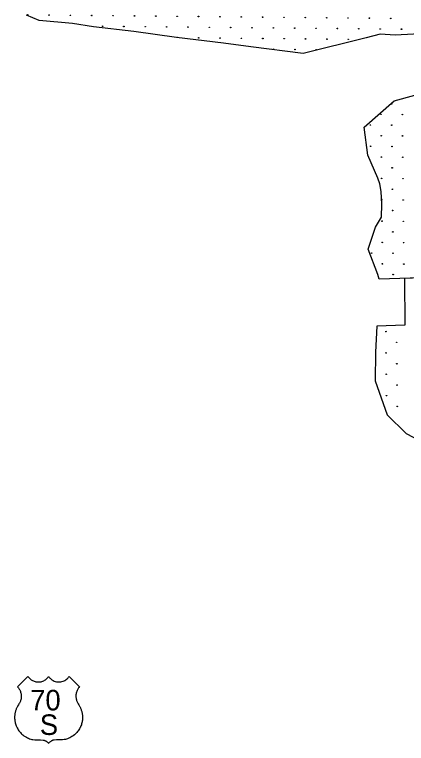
# Model space of a CAD drawing. Extents: x 1612280 to 1883141, y 560852 to 780851.
# Drawn here: x 1777552 to 1784608, y 634420 to 647547 of the extents above; entities that cross this region are included whole.
import ezdxf

# ---------------------------------------------------------------- set-up
doc = ezdxf.new("R2010")
doc.units = 0
for name, color, linetype in [('DESIGN - EROSION CONTROL - Devices', 7, 'Continuous'), ('DESIGN - SCRATCH - User 1', 7, 'Continuous'), ('SURVEY - DRAINAGE - Bridge Deck with Text', 7, 'Continuous')]:
    doc.layers.add(name, color=color, linetype=linetype)

msp = doc.modelspace()

# ---------------------------------------------------------------- linework, layer by layer
at = {"layer": 'DESIGN - EROSION CONTROL - Devices'}
for centre in [(1777788, 647542), (1777788, 647542), (1778173, 647538), (1778173, 647538), (1778557, 647534), (1778557, 647534), (1778942, 647531), (1778942, 647531), (1779326, 647527), (1779326, 647527), (1779711, 647523), (1779711, 647523), (1780095, 647520), (1780095, 647520), (1780480, 647516), (1780480, 647516), (1780864, 647512), (1780864, 647512), (1781249, 647508), (1781249, 647508), (1781634, 647505), (1781634, 647505), (1782018, 647501), (1782018, 647501), (1782403, 647497), (1782403, 647497), (1782787, 647493), (1782787, 647493), (1783172, 647490), (1783172, 647490), (1783556, 647486), (1783556, 647486), (1783941, 647482), (1783941, 647482), (1784325, 647478), (1784325, 647478), (1779136, 647337), (1779136, 647337), (1779520, 647333), (1779520, 647333), (1779905, 647329), (1779905, 647329), (1780290, 647325), (1780290, 647325), (1780674, 647322), (1780674, 647322), (1781059, 647318), (1781059, 647318), (1781443, 647314), (1781443, 647314), (1781828, 647310), (1781828, 647310), (1782212, 647307), (1782212, 647307), (1782597, 647303), (1782597, 647303), (1782981, 647299), (1782981, 647299), (1783366, 647296), (1783366, 647296), (1783750, 647292), (1783750, 647292), (1784135, 647288), (1784135, 647288), (1784520, 647284), (1784520, 647284), (1780868, 647128), (1780868, 647128), (1781253, 647124), (1781253, 647124), (1781637, 647120), (1781637, 647120), (1782022, 647116), (1782022, 647116), (1782406, 647113), (1782406, 647113), (1782791, 647109), (1782791, 647109), (1783176, 647105), (1783176, 647105), (1783560, 647101), (1783560, 647101), (1782216, 646922), (1782216, 646922), (1782601, 646918), (1782601, 646918), (1782985, 646915), (1782985, 646915), (1784340, 645940), (1784340, 645940), (1784150, 645750), (1784150, 645750), (1784535, 645746), (1784535, 645746), (1783960, 645559), (1783960, 645559), (1784344, 645556), (1784344, 645556), (1784154, 645365), (1784154, 645365), (1784538, 645362), (1784538, 645362), (1783963, 645175), (1783963, 645175), (1784348, 645171), (1784348, 645171), (1784157, 644981), (1784157, 644981), (1784542, 644977), (1784542, 644977), (1784352, 644787), (1784352, 644787), (1784161, 644596), (1784161, 644596), (1784546, 644592), (1784546, 644592), (1784355, 644402), (1784355, 644402), (1784549, 644208), (1784549, 644208), (1784359, 644018), (1784359, 644018), (1784169, 643827), (1784169, 643827), (1784553, 643823), (1784553, 643823), (1784363, 643633), (1784363, 643633), (1784172, 643443), (1784172, 643443), (1784557, 643439), (1784557, 643439), (1783982, 643252), (1783982, 643252), (1784367, 643248), (1784367, 643248), (1784176, 643058), (1784176, 643058), (1784561, 643054), (1784561, 643054), (1784370, 642864), (1784370, 642864), (1784238, 641838), (1784238, 641838), (1784432, 641644), (1784432, 641644), (1784242, 641453), (1784242, 641453), (1784436, 641259), (1784436, 641259), (1784245, 641069), (1784245, 641069), (1784440, 640875), (1784440, 640875), (1784249, 640684), (1784249, 640684), (1784443, 640490), (1784443, 640490)]:
    msp.add_circle(centre, 5.28, dxfattribs=at)
for centre, start, end in [((1780484, 647131), 31.7082, 134.4457), ((1784165, 644212), 227.1519, 136.8387), ((1784051, 641263), 268.7817, 89.7128)]:
    msp.add_arc(centre, 5.28, start, end, dxfattribs=at)
at = {"layer": 'DESIGN - SCRATCH - User 1'}
for points in [[(1782749, 646848), (1781805, 646967), (1781313, 647034), (1780468, 647136), (1779699, 647245), (1778975, 647327), (1778596, 647386), (1777996, 647440), (1777767, 647536)], [(1782749, 646848), (1781805, 646967), (1781313, 647034), (1780468, 647136), (1779699, 647245), (1778975, 647327), (1778596, 647386), (1777996, 647440), (1777767, 647536)], [(1785529, 646615), (1785148, 647210), (1784872, 647214), (1784737, 647197), (1784404, 647174), (1784134, 647194), (1783883, 647130), (1782749, 646848)], [(1785529, 646615), (1785148, 647210), (1784872, 647214), (1784737, 647197), (1784404, 647174), (1784134, 647194), (1783883, 647130), (1782749, 646848)], [(1783915, 645017), (1783846, 645521), (1784390, 645995), (1784757, 646095), (1785191, 646018), (1785253, 646128), (1785314, 646211), (1785505, 646578), (1785529, 646615)], [(1783915, 645017), (1783846, 645521), (1784390, 645995), (1784757, 646095), (1785191, 646018), (1785253, 646128), (1785314, 646211), (1785505, 646578), (1785529, 646615)], [(1784053, 643716), (1784157, 643897), (1784164, 644133), (1784156, 644358), (1784131, 644496), (1784094, 644600), (1783915, 645017)], [(1784053, 643716), (1784157, 643897), (1784164, 644133), (1784156, 644358), (1784131, 644496), (1784094, 644600), (1783915, 645017)], [(1784118, 642782), (1784093, 642868), (1783920, 643322), (1784053, 643716)], [(1784118, 642782), (1784093, 642868), (1783920, 643322), (1784053, 643716)], [(1784862, 642807), (1784118, 642782)], [(1784862, 642807), (1784118, 642782)], [(1784862, 642805), (1784571, 642796)], [(1784862, 642805), (1784571, 642796)], [(1784571, 642796), (1784578, 641955)], [(1784571, 642796), (1784578, 641955)], [(1784047, 640948), (1784263, 640340), (1784602, 640000), (1784616, 639999), (1785079, 639748), (1785285, 639699), (1785502, 639640), (1785551, 639856), (1785590, 639935), (1785796, 639900), (1785806, 639763), (1785698, 639724), (1785688, 639571), (1785732, 639483), (1786049, 639414), (1786490, 640106), (1786678, 640567), (1786844, 641009), (1786928, 641333), (1786935, 641371), (1787078, 641512), (1787202, 641773), (1787237, 642327)], [(1784047, 640948), (1784263, 640340), (1784602, 640000), (1784616, 639999), (1785079, 639748), (1785285, 639699), (1785502, 639640), (1785551, 639856), (1785590, 639935), (1785796, 639900), (1785806, 639763), (1785698, 639724), (1785688, 639571), (1785732, 639483), (1786049, 639414), (1786490, 640106), (1786678, 640567), (1786844, 641009), (1786928, 641333), (1786935, 641371), (1787078, 641512), (1787202, 641773), (1787237, 642327)], [(1784077, 641938), (1784054, 641465), (1784047, 640948), (1784047, 640945)], [(1784077, 641938), (1784054, 641465), (1784047, 640948), (1784047, 640945)], [(1784578, 641955), (1784077, 641938)], [(1784578, 641955), (1784077, 641938)]]:
    msp.add_lwpolyline(points, dxfattribs=at)
at = {"layer": 'SURVEY - DRAINAGE - Bridge Deck with Text'}
for points in [[(1777606, 635441), (1777793, 635627), (1777803, 635614), (1777816, 635599), (1777828, 635587), (1777839, 635577), (1777851, 635567), (1777864, 635559), (1777876, 635552), (1777891, 635545), (1777904, 635540), (1777920, 635535), (1777936, 635531), (1777953, 635528), (1777970, 635527), (1777978, 635527), (1777986, 635527), (1777994, 635527), (1778004, 635528), (1778015, 635530), (1778028, 635532), (1778041, 635536), (1778059, 635542), (1778076, 635549), (1778093, 635558), (1778106, 635567), (1778120, 635578), (1778134, 635589), (1778146, 635602), (1778157, 635616), (1778165, 635627), (1778171, 635617), (1778180, 635606), (1778188, 635597), (1778197, 635588), (1778209, 635577), (1778222, 635568), (1778235, 635559), (1778248, 635552), (1778264, 635544), (1778283, 635537), (1778304, 635532), (1778325, 635528), (1778343, 635527), (1778363, 635527), (1778383, 635529), (1778403, 635533), (1778426, 635540), (1778443, 635547), (1778458, 635555), (1778475, 635565), (1778489, 635576), (1778505, 635590), (1778516, 635601), (1778526, 635613), (1778536, 635627), (1778723, 635441)], [(1777606, 635441), (1777793, 635627), (1777803, 635614), (1777816, 635599), (1777828, 635587), (1777839, 635577), (1777851, 635567), (1777864, 635559), (1777876, 635552), (1777891, 635545), (1777904, 635540), (1777920, 635535), (1777936, 635531), (1777953, 635528), (1777970, 635527), (1777978, 635527), (1777986, 635527), (1777994, 635527), (1778004, 635528), (1778015, 635530), (1778028, 635532), (1778041, 635536), (1778059, 635542), (1778076, 635549), (1778093, 635558), (1778106, 635567), (1778120, 635578), (1778134, 635589), (1778146, 635602), (1778157, 635616), (1778165, 635627), (1778171, 635617), (1778180, 635606), (1778188, 635597), (1778197, 635588), (1778209, 635577), (1778222, 635568), (1778235, 635559), (1778248, 635552), (1778264, 635544), (1778283, 635537), (1778304, 635532), (1778325, 635528), (1778343, 635527), (1778363, 635527), (1778383, 635529), (1778403, 635533), (1778426, 635540), (1778443, 635547), (1778458, 635555), (1778475, 635565), (1778489, 635576), (1778505, 635590), (1778516, 635601), (1778526, 635613), (1778536, 635627), (1778723, 635441)], [(1777606, 635441), (1777615, 635430), (1777623, 635420), (1777631, 635408), (1777637, 635398), (1777644, 635386), (1777651, 635372), (1777656, 635358), (1777661, 635342), (1777665, 635328), (1777668, 635312), (1777671, 635294), (1777672, 635272), (1777671, 635256), (1777670, 635240), (1777668, 635226), (1777664, 635208), (1777660, 635194), (1777656, 635181), (1777651, 635169), (1777646, 635158), (1777638, 635145), (1777631, 635132), (1777620, 635114), (1777607, 635093), (1777604, 635087), (1777598, 635076), (1777591, 635063), (1777587, 635054), (1777582, 635043), (1777578, 635032), (1777574, 635021), (1777570, 635010), (1777567, 634997), (1777563, 634984), (1777561, 634973), (1777558, 634960), (1777556, 634949), (1777555, 634936), (1777554, 634924), (1777553, 634913), (1777552, 634902), (1777552, 634891), (1777552, 634878), (1777553, 634867), (1777554, 634852), (1777555, 634837), (1777558, 634822), (1777560, 634807), (1777564, 634791), (1777569, 634772), (1777574, 634757), (1777580, 634739), (1777586, 634726), (1777591, 634714), (1777599, 634700), (1777609, 634682), (1777618, 634667), (1777630, 634650), (1777642, 634634), (1777656, 634617), (1777670, 634602), (1777683, 634590), (1777700, 634575), (1777720, 634560), (1777744, 634544), (1777764, 634532), (1777783, 634522), (1777802, 634514), (1777822, 634506), (1777842, 634499), (1777861, 634494), (1777871, 634492), (1777883, 634490), (1777914, 634487), (1778019, 634484), (1778067, 634482), (1778071, 634481), (1778076, 634480), (1778081, 634479), (1778086, 634477), (1778091, 634476), (1778096, 634474), (1778101, 634472), (1778105, 634470), (1778111, 634467), (1778114, 634465), (1778118, 634463), (1778127, 634458), (1778136, 634451), (1778145, 634444), (1778152, 634436), (1778159, 634429), (1778164, 634420)], [(1777606, 635441), (1777615, 635430), (1777623, 635420), (1777631, 635408), (1777637, 635398), (1777644, 635386), (1777651, 635372), (1777656, 635358), (1777661, 635342), (1777665, 635328), (1777668, 635312), (1777671, 635294), (1777672, 635272), (1777671, 635256), (1777670, 635240), (1777668, 635226), (1777664, 635208), (1777660, 635194), (1777656, 635181), (1777651, 635169), (1777646, 635158), (1777638, 635145), (1777631, 635132), (1777620, 635114), (1777607, 635093), (1777604, 635087), (1777598, 635076), (1777591, 635063), (1777587, 635054), (1777582, 635043), (1777578, 635032), (1777574, 635021), (1777570, 635010), (1777567, 634997), (1777563, 634984), (1777561, 634973), (1777558, 634960), (1777556, 634949), (1777555, 634936), (1777554, 634924), (1777553, 634913), (1777552, 634902), (1777552, 634891), (1777552, 634878), (1777553, 634867), (1777554, 634852), (1777555, 634837), (1777558, 634822), (1777560, 634807), (1777564, 634791), (1777569, 634772), (1777574, 634757), (1777580, 634739), (1777586, 634726), (1777591, 634714), (1777599, 634700), (1777609, 634682), (1777618, 634667), (1777630, 634650), (1777642, 634634), (1777656, 634617), (1777670, 634602), (1777683, 634590), (1777700, 634575), (1777720, 634560), (1777744, 634544), (1777764, 634532), (1777783, 634522), (1777802, 634514), (1777822, 634506), (1777842, 634499), (1777861, 634494), (1777871, 634492), (1777883, 634490), (1777914, 634487), (1778019, 634484), (1778067, 634482), (1778071, 634481), (1778076, 634480), (1778081, 634479), (1778086, 634477), (1778091, 634476), (1778096, 634474), (1778101, 634472), (1778105, 634470), (1778111, 634467), (1778114, 634465), (1778118, 634463), (1778127, 634458), (1778136, 634451), (1778145, 634444), (1778152, 634436), (1778159, 634429), (1778164, 634420)], [(1778723, 635441), (1778713, 635430), (1778705, 635420), (1778698, 635408), (1778691, 635398), (1778684, 635386), (1778678, 635372), (1778672, 635358), (1778667, 635342), (1778663, 635328), (1778660, 635312), (1778658, 635294), (1778657, 635272), (1778657, 635256), (1778659, 635240), (1778661, 635226), (1778665, 635208), (1778669, 635194), (1778673, 635181), (1778678, 635169), (1778683, 635158), (1778691, 635145), (1778698, 635132), (1778708, 635114), (1778721, 635093), (1778725, 635087), (1778731, 635076), (1778737, 635063), (1778741, 635054), (1778746, 635043), (1778750, 635032), (1778754, 635022), (1778758, 635010), (1778762, 634997), (1778765, 634984), (1778768, 634973), (1778770, 634961), (1778772, 634949), (1778774, 634936), (1778775, 634924), (1778776, 634913), (1778776, 634902), (1778777, 634891), (1778776, 634878), (1778776, 634867), (1778775, 634852), (1778773, 634837), (1778771, 634822), (1778768, 634807), (1778765, 634791), (1778759, 634772), (1778755, 634757), (1778748, 634740), (1778742, 634726), (1778737, 634714), (1778730, 634700), (1778720, 634682), (1778711, 634667), (1778699, 634650), (1778686, 634634), (1778673, 634617), (1778658, 634602), (1778646, 634590), (1778629, 634575), (1778609, 634560), (1778585, 634544), (1778565, 634532), (1778545, 634522), (1778527, 634514), (1778506, 634506), (1778487, 634499), (1778468, 634494), (1778458, 634492), (1778445, 634490), (1778415, 634487), (1778309, 634484), (1778262, 634482), (1778257, 634481), (1778252, 634480), (1778247, 634479), (1778242, 634477), (1778237, 634476), (1778233, 634474), (1778228, 634472), (1778223, 634470), (1778218, 634467), (1778214, 634465), (1778210, 634463), (1778202, 634458), (1778192, 634451), (1778184, 634444), (1778176, 634436), (1778170, 634429), (1778164, 634420)], [(1778723, 635441), (1778713, 635430), (1778705, 635420), (1778698, 635408), (1778691, 635398), (1778684, 635386), (1778678, 635372), (1778672, 635358), (1778667, 635342), (1778663, 635328), (1778660, 635312), (1778658, 635294), (1778657, 635272), (1778657, 635256), (1778659, 635240), (1778661, 635226), (1778665, 635208), (1778669, 635194), (1778673, 635181), (1778678, 635169), (1778683, 635158), (1778691, 635145), (1778698, 635132), (1778708, 635114), (1778721, 635093), (1778725, 635087), (1778731, 635076), (1778737, 635063), (1778741, 635054), (1778746, 635043), (1778750, 635032), (1778754, 635022), (1778758, 635010), (1778762, 634997), (1778765, 634984), (1778768, 634973), (1778770, 634961), (1778772, 634949), (1778774, 634936), (1778775, 634924), (1778776, 634913), (1778776, 634902), (1778777, 634891), (1778776, 634878), (1778776, 634867), (1778775, 634852), (1778773, 634837), (1778771, 634822), (1778768, 634807), (1778765, 634791), (1778759, 634772), (1778755, 634757), (1778748, 634740), (1778742, 634726), (1778737, 634714), (1778730, 634700), (1778720, 634682), (1778711, 634667), (1778699, 634650), (1778686, 634634), (1778673, 634617), (1778658, 634602), (1778646, 634590), (1778629, 634575), (1778609, 634560), (1778585, 634544), (1778565, 634532), (1778545, 634522), (1778527, 634514), (1778506, 634506), (1778487, 634499), (1778468, 634494), (1778458, 634492), (1778445, 634490), (1778415, 634487), (1778309, 634484), (1778262, 634482), (1778257, 634481), (1778252, 634480), (1778247, 634479), (1778242, 634477), (1778237, 634476), (1778233, 634474), (1778228, 634472), (1778223, 634470), (1778218, 634467), (1778214, 634465), (1778210, 634463), (1778202, 634458), (1778192, 634451), (1778184, 634444), (1778176, 634436), (1778170, 634429), (1778164, 634420)]]:
    msp.add_lwpolyline(points, dxfattribs=at)

# ---------------------------------------------------------------- texts
for s, height, p in [('70', 369.6, (1777832, 635015)), ('70', 369.6, (1777832, 635015)), ('S', 370, (1778006, 634573)), ('S', 370, (1778006, 634573))]:
    msp.add_text(s, height=height, rotation=0.0014, dxfattribs=at).set_placement(p)

doc.saveas('drawing.dxf')
